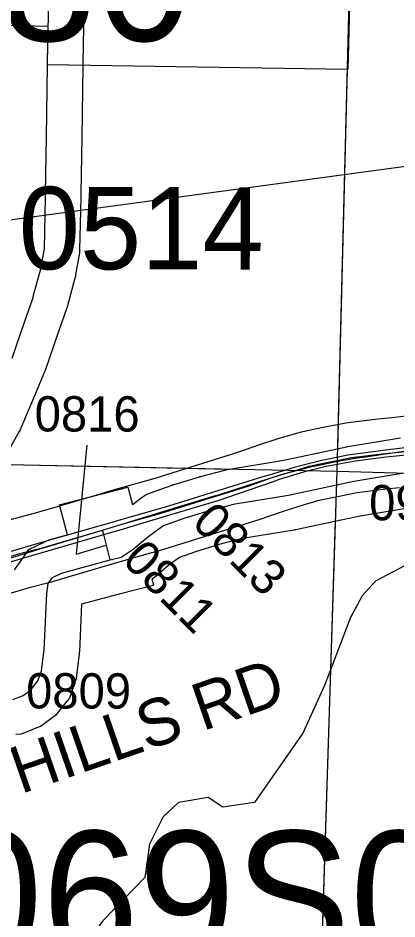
# Model space of a CAD drawing. Extents: x -132.8 to -73.3, y -60 to -26.
# Drawn here: x -120.22 to -119.898, y -51.702 to -50.936 of the extents above; entities that cross this region are included whole.
import ezdxf

# ---------------------------------------------------------------- set-up
doc = ezdxf.new("R2010")
doc.units = 0
for name, color, linetype in [('tdCoCityStreetMajor', 7, 'Continuous'), ('tdCoCorpBndry', 7, 'Continuous'), ('tdCoDivCarto', 7, 'Continuous'), ('tdCoHydroRiver', 7, 'Continuous'), ('tdCoPriCL', 7, 'Continuous'), ('tdCoPriDiv', 7, 'Continuous'), ('tdCoPrimary', 7, 'Continuous'), ('tdCoSecRdNmbr', 7, 'Continuous'), ('tdCoSecRdTxt', 7, 'Continuous'), ('tdCoSecRteBand', 7, 'Continuous'), ('tdCoSecRteCL', 7, 'Continuous'), ('tdCoSectLine', 7, 'Continuous'), ('tdCoSectLinePart', 7, 'Continuous'), ('tdCoStrucPriMaintName', 7, 'Continuous'), ('tdCoSurfBitum', 7, 'Continuous'), ('tdCoSurfConc', 7, 'Continuous')]:
    doc.layers.add(name, color=color, linetype=linetype)

msp = doc.modelspace()

# ---------------------------------------------------------------- linework, layer by layer
at = {"layer": 'tdCoCityStreetMajor'}
msp.add_lwpolyline([(-120.19402, -50.94361), (-120.1939, -50.93753), (-120.19341, -50.91567)], dxfattribs=at)
at = {"layer": 'tdCoCorpBndry'}
msp.add_lwpolyline([(-119.93545, -50.82782), (-119.93937, -50.98007), (-120.19465, -50.97611), (-120.19439, -50.95902), (-120.19404, -50.94356), (-120.20555, -50.94338), (-120.3235, -50.94019)], dxfattribs=at)
at = {"layer": 'tdCoDivCarto'}
for points in [[(-119.86963, -51.29922), (-119.90523, -51.30326), (-119.93951, -51.30795), (-119.95881, -51.31176)], [(-119.95881, -51.31176), (-119.96072, -51.31214), (-119.98513, -51.31855), (-120.00544, -51.32457)], [(-119.95774, -51.31733), (-119.93285, -51.31263), (-119.90696, -51.30943), (-119.88698, -51.30745), (-119.86895, -51.30593)], [(-120.00354, -51.33051), (-119.99746, -51.32842), (-119.97403, -51.32126), (-119.95899, -51.31756), (-119.95774, -51.31733)], [(-120.00544, -51.32457), (-120.01176, -51.32644), (-120.02448, -51.33036)], [(-120.02448, -51.33036), (-120.09564, -51.35229)], [(-120.02234, -51.33698), (-120.00354, -51.33051)], [(-120.09342, -51.35956), (-120.04974, -51.34642), (-120.02234, -51.33698)], [(-120.09564, -51.35229), (-120.0998, -51.35357), (-120.13242, -51.36294)], [(-120.13242, -51.36294), (-120.1489, -51.36768), (-120.14902, -51.36771)], [(-120.13023, -51.37048), (-120.11041, -51.36467), (-120.09342, -51.35956)], [(-120.14902, -51.36771), (-120.18384, -51.37772)], [(-120.1468, -51.37534), (-120.13023, -51.37048)], [(-120.18384, -51.37772), (-120.20362, -51.38341), (-120.21911, -51.3879)], [(-120.18157, -51.38554), (-120.14692, -51.37538), (-120.1468, -51.37534)], [(-120.21911, -51.3879), (-120.23662, -51.39298)], [(-120.21679, -51.39587), (-120.18157, -51.38554)], [(-120.2344, -51.40083), (-120.22138, -51.39722), (-120.21679, -51.39587)]]:
    msp.add_lwpolyline(points, dxfattribs=at)
at = {"layer": 'tdCoHydroRiver'}
msp.add_lwpolyline([(-119.85658, -51.38355), (-119.91583, -51.41508), (-119.92721, -51.4274), (-119.93718, -51.44606), (-119.95925, -51.50384), (-119.9777, -51.54437), (-120.01874, -51.60322), (-120.04568, -51.60723), (-120.05809, -51.599), (-120.08345, -51.60305), (-120.09641, -51.61533), (-120.10808, -51.63868), (-120.112, -51.66697), (-120.14772, -51.70388), (-120.16246, -51.72399), (-120.16995, -51.76797), (-120.20315, -51.82861), (-120.20715, -51.86005), (-120.19973, -51.87761), (-120.19431, -51.91089), (-120.20781, -51.94366)], dxfattribs=at)
at = {"layer": 'tdCoPriCL'}
msp.add_lwpolyline([(-119.87773, -51.30356), (-119.8988, -51.30594), (-119.91052, -51.30714), (-119.93636, -51.31032), (-119.95861, -51.31469), (-119.97272, -51.31767), (-119.99001, -51.32284), (-120.00492, -51.32761), (-120.02366, -51.33424), (-120.09475, -51.35642), (-120.10429, -51.3592), (-120.13167, -51.36686), (-120.1482, -51.37186), (-120.18297, -51.38206), (-120.20027, -51.38713), (-120.21836, -51.3918), (-120.23585, -51.39696)], dxfattribs=at)
at = {"layer": 'tdCoPriDiv'}
for points in [[(-119.88025, -51.27365), (-119.902, -51.27611), (-119.91387, -51.27732), (-119.94109, -51.28067), (-119.96461, -51.28529), (-119.98013, -51.28857), (-119.99888, -51.29417), (-120.0145, -51.29917), (-120.03314, -51.30577), (-120.10342, -51.3277), (-120.11253, -51.33036), (-120.14005, -51.33806), (-120.15677, -51.3431), (-120.19141, -51.35327), (-120.20823, -51.3582), (-120.22636, -51.36288)], [(-119.89559, -51.33577), (-119.90717, -51.33695), (-119.93163, -51.33996), (-119.95262, -51.34408), (-119.96532, -51.34677), (-119.98115, -51.3515), (-119.99534, -51.35604), (-120.01418, -51.36271), (-120.08608, -51.38514), (-120.09605, -51.38805), (-120.1233, -51.39567), (-120.13964, -51.40061), (-120.17453, -51.41085), (-120.1923, -51.41605), (-120.21036, -51.42072), (-120.22761, -51.42581)]]:
    msp.add_lwpolyline(points, dxfattribs=at)
at = {"layer": 'tdCoPrimary'}
for p, q in [((-120.10195, -51.35761), (-120.05466, -51.34315)), ((-120.10195, -51.35761), (-120.05466, -51.34315)), ((-120.05466, -51.34315), (-120.05169, -51.34224)), ((-120.05466, -51.34315), (-120.05169, -51.34224)), ((-120.14788, -51.37166), (-120.10195, -51.35761)), ((-120.14788, -51.37166), (-120.10195, -51.35761)), ((-120.20293, -51.38825), (-120.14788, -51.37166)), ((-120.20293, -51.38825), (-120.14788, -51.37166)), ((-120.20832, -51.38988), (-120.20293, -51.38825)), ((-120.20832, -51.38988), (-120.20293, -51.38825))]:
    msp.add_line(p, q, dxfattribs=at)
for points in [[(-120.22952, -51.39627), (-120.20832, -51.38988), (-120.20293, -51.38825), (-120.14788, -51.37166), (-120.10195, -51.35761), (-120.05466, -51.34315), (-120.05169, -51.34224), (-120.04933, -51.34152), (-120.01464, -51.33034), (-119.99294, -51.3236), (-119.97009, -51.31768), (-119.96115, -51.31585), (-119.95085, -51.31373), (-119.93359, -51.31061), (-119.92417, -51.30924), (-119.90762, -51.30683), (-119.88805, -51.30403)], [(-119.92417, -51.30924), (-119.90762, -51.30683), (-119.88805, -51.30403), (-119.86684, -51.30206), (-119.86444, -51.30191)], [(-119.92417, -51.30924), (-119.90762, -51.30683), (-119.88805, -51.30403), (-119.86684, -51.30206), (-119.86444, -51.30191)], [(-119.96115, -51.31585), (-119.95085, -51.31373), (-119.93359, -51.31061), (-119.92417, -51.30924)], [(-119.96115, -51.31585), (-119.95085, -51.31373), (-119.93359, -51.31061), (-119.92417, -51.30924)], [(-120.05169, -51.34224), (-120.04933, -51.34152), (-120.01464, -51.33034), (-119.99294, -51.3236), (-119.97009, -51.31768), (-119.96115, -51.31585)], [(-120.05169, -51.34224), (-120.04933, -51.34152), (-120.01464, -51.33034), (-119.99294, -51.3236), (-119.97009, -51.31768), (-119.96115, -51.31585)], [(-120.29943, -51.41718), (-120.22952, -51.39627), (-120.20832, -51.38988)], [(-120.29943, -51.41718), (-120.22952, -51.39627), (-120.20832, -51.38988)]]:
    msp.add_lwpolyline(points, dxfattribs=at)
at = {"layer": 'tdCoSecRdNmbr'}
msp.add_lwpolyline([(-120.16124, -51.29955), (-120.1702, -51.39221), (-120.14496, -51.38444)], dxfattribs=at)
at = {"layer": 'tdCoSecRteBand'}
for points in [[(-120.16344, -50.9142), (-120.16403, -50.94419), (-120.16461, -50.97422), (-120.16465, -50.97656), (-120.16559, -51.038), (-120.16631, -51.08529), (-120.16636, -51.08894), (-120.16636, -51.08905), (-120.16637, -51.08916), (-120.16735, -51.1333), (-120.1674, -51.13555), (-120.16779, -51.13777), (-120.16801, -51.13907), (-120.17075, -51.15478), (-120.17099, -51.15619), (-120.17137, -51.15756), (-120.17778, -51.18099), (-120.17804, -51.18192), (-120.17835, -51.18284), (-120.17862, -51.18363), (-120.18584, -51.20458), (-120.19635, -51.23512), (-120.19669, -51.23609), (-120.19709, -51.23703), (-120.20287, -51.25071), (-120.21731, -51.28487), (-120.21796, -51.28642), (-120.21879, -51.28789), (-120.2282, -51.30464)], [(-120.2228, -51.40549), (-120.21855, -51.39954), (-120.21485, -51.39436), (-120.2104, -51.38813), (-120.20351, -51.38479), (-120.19586, -51.38109), (-120.19329, -51.37985), (-120.19053, -51.37911), (-120.17806, -51.37578), (-120.17781, -51.37571), (-120.18441, -51.3501), (-120.12631, -51.33513), (-120.12255, -51.34974), (-120.11421, -51.34376), (-120.11087, -51.34137), (-120.10701, -51.33996), (-120.08876, -51.3333), (-120.08793, -51.333), (-120.08707, -51.33274), (-120.06562, -51.32633), (-120.06512, -51.32618), (-120.06461, -51.32605), (-120.04291, -51.32038), (-120.04155, -51.32002), (-120.04015, -51.31979), (-119.9955, -51.31251), (-119.98317, -51.30988), (-119.94072, -51.30083), (-119.94005, -51.30068), (-119.93937, -51.30057), (-119.89473, -51.29317)], [(-119.88637, -51.35261), (-119.92888, -51.35965), (-119.97065, -51.36856), (-119.98369, -51.37134), (-119.9844, -51.3715), (-119.98512, -51.37161), (-120.0291, -51.37878), (-120.04894, -51.38397), (-120.06904, -51.38997), (-120.08259, -51.39492), (-120.09126, -51.40114), (-120.10236, -51.41065), (-120.1038, -51.41189), (-120.10538, -51.41293), (-120.10594, -51.4133), (-120.10461, -51.41827), (-120.10486, -51.41834), (-120.1048, -51.41859), (-120.13373, -51.42604), (-120.16576, -51.4346), (-120.16762, -51.47484), (-120.16768, -51.47601), (-120.16782, -51.47717), (-120.17004, -51.49492), (-120.17043, -51.498), (-120.17143, -51.50093), (-120.17439, -51.50956), (-120.17609, -51.5145), (-120.17934, -51.51857), (-120.18526, -51.52597), (-120.1877, -51.52902), (-120.19083, -51.53134), (-120.19749, -51.53627), (-120.20072, -51.53866), (-120.20447, -51.54012), (-120.21335, -51.54358), (-120.2173, -51.54511), (-120.22151, -51.54549)]]:
    msp.add_lwpolyline(points, dxfattribs=at)
at = {"layer": 'tdCoSecRteCL'}
for points in [[(-120.22472, -51.22535), (-120.2142, -51.19482), (-120.20699, -51.17386), (-120.20672, -51.17307), (-120.2003, -51.14964), (-120.19757, -51.13393), (-120.19735, -51.13263), (-120.19636, -51.08848), (-120.1963, -51.08483), (-120.19558, -51.03754), (-120.19465, -50.97611), (-120.19461, -50.97369), (-120.19402, -50.94361)], [(-120.14134, -51.39703), (-120.13199, -51.39453), (-120.12188, -51.38787), (-120.1098, -51.37752), (-120.09673, -51.36814), (-120.07848, -51.36149), (-120.05703, -51.35507), (-120.03533, -51.3494), (-119.98995, -51.342), (-119.97691, -51.33922), (-119.93446, -51.33017), (-119.88983, -51.32277)], [(-120.14134, -51.39703), (-120.14692, -51.37538), (-120.14788, -51.37166)], [(-120.22423, -51.51562), (-120.21535, -51.51216), (-120.20869, -51.50723), (-120.20277, -51.49983), (-120.19981, -51.4912), (-120.19759, -51.47345), (-120.19537, -51.4256), (-120.19414, -51.41697), (-120.19044, -51.41179), (-120.1828, -51.4081), (-120.14134, -51.39703)]]:
    msp.add_lwpolyline(points, dxfattribs=at)
at = {"layer": 'tdCoSectLine'}
for points in [[(-119.94854, -51.32154), (-119.93626, -50.84463), (-119.92398, -50.36772)], [(-120.95707, -51.30108), (-120.4528, -51.31131), (-119.94854, -51.32154)], [(-119.98023, -52.31774), (-119.94854, -51.32154)], [(-119.94854, -51.32154), (-119.45745, -51.33549), (-118.96636, -51.34945)]]:
    msp.add_lwpolyline(points, dxfattribs=at)
at = {"layer": 'tdCoSectLinePart'}
for points in [[(-119.94804, -51.30223), (-119.9366, -50.85777)], [(-120.22868, -51.31586), (-120.03914, -51.3197)], [(-119.96648, -51.88565), (-119.94989, -51.36394)]]:
    msp.add_lwpolyline(points, dxfattribs=at)
at = {"layer": 'tdCoStrucPriMaintName'}
msp.add_line((-119.01171, -50.94258), (-122.36402, -51.39975), dxfattribs=at)
msp.add_line((-119.01171, -50.94258), (-122.36402, -51.39975), dxfattribs=at)
msp.add_line((-119.01171, -50.94258), (-122.36402, -51.39975), dxfattribs=at)
at = {"layer": 'tdCoSurfBitum'}
msp.add_lwpolyline([(-120.22472, -51.22535), (-120.2142, -51.19482), (-120.20699, -51.17386), (-120.20672, -51.17307), (-120.2003, -51.14964), (-120.19757, -51.13393), (-120.19735, -51.13263), (-120.19636, -51.08848), (-120.1963, -51.08483), (-120.19558, -51.03754), (-120.19465, -50.97611), (-120.19461, -50.97369), (-120.19402, -50.94361)], dxfattribs=at)
at = {"layer": 'tdCoSurfConc'}
for points in [[(-120.14134, -51.39703), (-120.13199, -51.39453), (-120.12188, -51.38787), (-120.1098, -51.37752), (-120.09673, -51.36814), (-120.07848, -51.36149), (-120.05703, -51.35507), (-120.03533, -51.3494), (-119.98995, -51.342), (-119.97691, -51.33922), (-119.93446, -51.33017), (-119.88983, -51.32277)], [(-120.14134, -51.39703), (-120.14692, -51.37538), (-120.14788, -51.37166)], [(-120.22423, -51.51562), (-120.21535, -51.51216), (-120.20869, -51.50723), (-120.20277, -51.49983), (-120.19981, -51.4912), (-120.19759, -51.47345), (-120.19537, -51.4256), (-120.19414, -51.41697), (-120.19044, -51.41179), (-120.1828, -51.4081), (-120.14134, -51.39703)]]:
    msp.add_lwpolyline(points, dxfattribs=at)

# ---------------------------------------------------------------- texts
at = {"layer": 'tdCoSecRdNmbr'}
for s, height, rotation, p in [('0514', 0.07, 359.91033, (-120.2192, -51.14985)), ('0816', 0.03, 359.9104, (-120.20562, -51.28775)), ('0903', 0.03, 359.91051, (-119.92138, -51.36325)), ('0813', 0.03, 314.91042, (-120.07315, -51.36638)), ('0811', 0.03, 314.91033, (-120.13229, -51.39831)), ('0809', 0.03, 359.91023, (-120.21292, -51.52323))]:
    msp.add_text(s, height=height, rotation=rotation, dxfattribs=at).set_placement(p)
at = {"layer": 'tdCoSecRdTxt'}
msp.add_text('VIRGINIA HILLS RD', height=0.04, rotation=19.11188, dxfattribs=at).set_placement((-120.45334, -51.67792))
at = {"layer": 'tdCoStrucPriMaintName'}
for s, p in [('78___080', (-120.72581, -50.95575)), ('78___080', (-120.72581, -50.95575)), ('78069S092', (-120.44445, -51.73739)), ('78069S092', (-120.44445, -51.73739)), ('78069S092', (-120.44445, -51.73739))]:
    msp.add_text(s, height=0.11, dxfattribs=at).set_placement(p)

doc.saveas('drawing.dxf')
